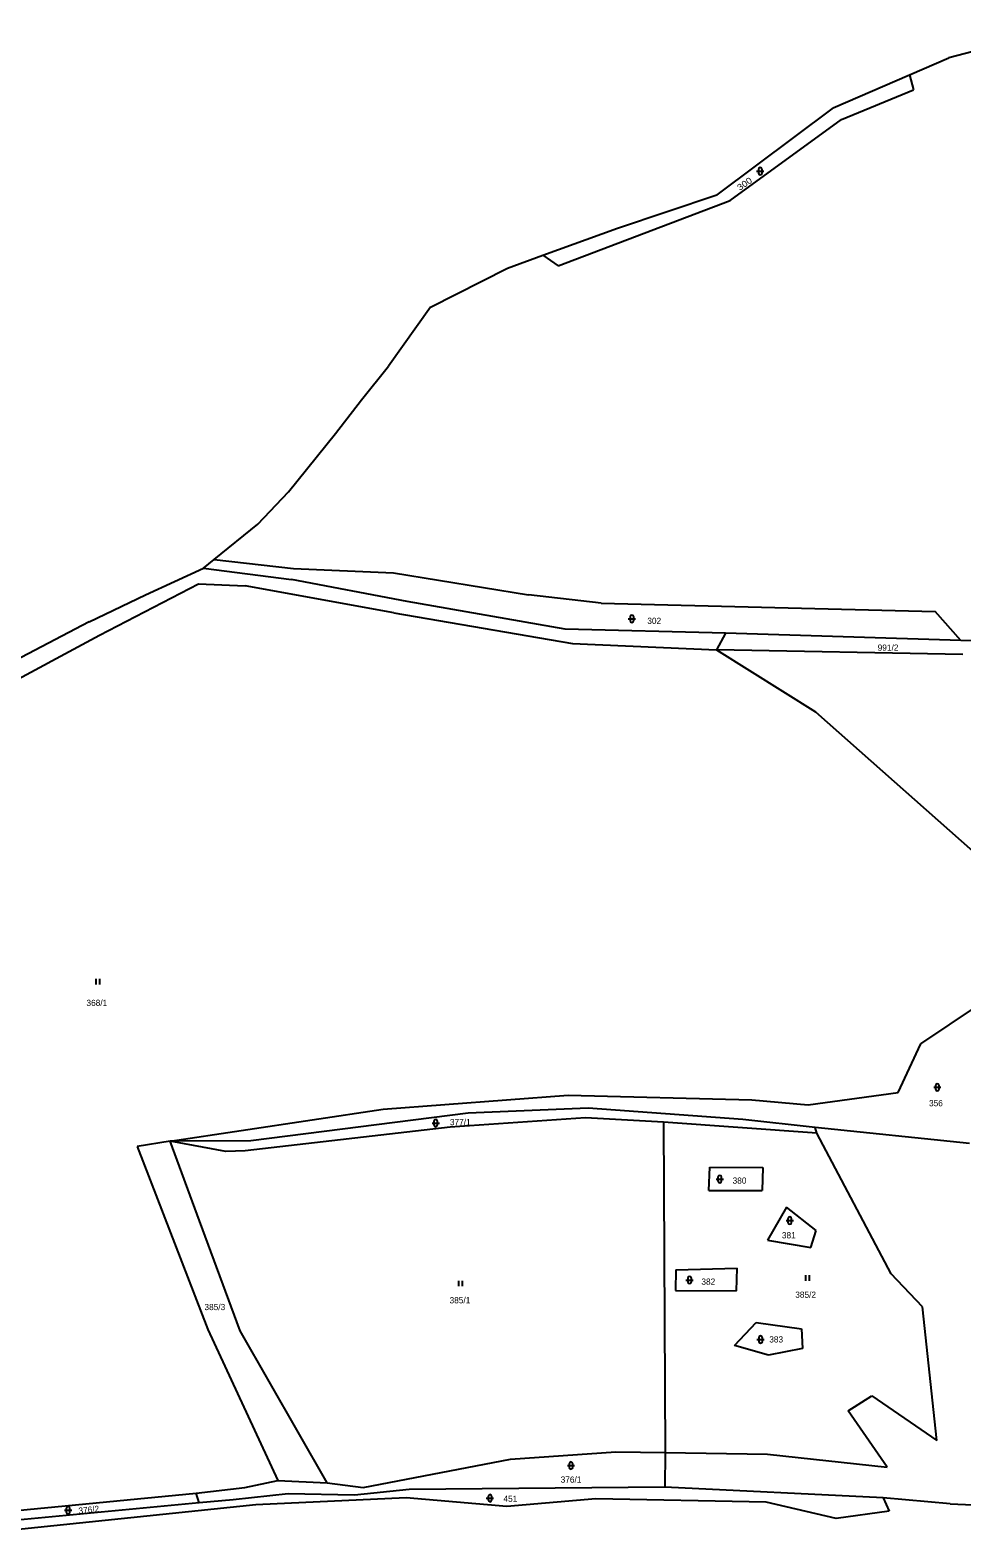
# Model space of a CAD drawing. Extents: x -754970 to -752637, y -970569 to -968179.
# Drawn here: x -754714.7 to -754459.1, y -968941.1 to -968527.7 of the extents above; entities that cross this region are included whole.
import ezdxf
from ezdxf.enums import TextEntityAlignment as Align

# ---------------------------------------------------------------- set-up
doc = ezdxf.new("R2010")
doc.units = 0
doc.header["$LTSCALE"] = 0.68
doc.layers.add('1', color=7, linetype='Continuous', lineweight=25)
doc.layers.add('3', color=7, linetype='Continuous', lineweight=25)
doc.layers.add('2', color=7, linetype='Continuous')

msp = doc.modelspace()

# ---------------------------------------------------------------- linework, layer by layer
at = {"layer": '1'}
for p, q in [((-754433.35, -968527.73), (-754462.74, -968535.32)), ((-754473.53, -968539.98), (-754462.74, -968535.32)), ((-754494.43, -968549), (-754473.53, -968539.98)), ((-754473.53, -968539.98), (-754472.43, -968544.13)), ((-754492.12, -968552.24), (-754472.43, -968544.13)), ((-754494.43, -968549), (-754526.37, -968572.84)), ((-754522.74, -968574.42), (-754492.12, -968552.24)), ((-754569.9, -968592.3), (-754522.74, -968574.42)), ((-754553.62, -968582), (-754526.37, -968572.84)), ((-754574.1, -968589.45), (-754553.62, -968582)), ((-754604.87, -968603.65), (-754583.78, -968592.98)), ((-754583.78, -968592.98), (-754574.1, -968589.45)), ((-754574.1, -968589.45), (-754569.9, -968592.3)), ((-754604.87, -968603.65), (-754616.39, -968619.89)), ((-754623.78, -968629.11), (-754616.39, -968619.89)), ((-754630.93, -968638.35), (-754623.78, -968629.11)), ((-754643.79, -968654.35), (-754630.93, -968638.35)), ((-754652.28, -968663.17), (-754643.79, -968654.35)), ((-754664.19, -968672.82), (-754652.28, -968663.17)), ((-754683.05, -968682.52), (-754667.13, -968675.2)), ((-754667.13, -968675.2), (-754664.19, -968672.82)), ((-754667.13, -968675.2), (-754643.04, -968678.37)), ((-754664.19, -968672.82), (-754642.5, -968675.3)), ((-754642.5, -968675.3), (-754615.07, -968676.54)), ((-754695.67, -968693.59), (-754668.51, -968679.52)), ((-754668.51, -968679.52), (-754655.68, -968680.06)), ((-754614.98, -968687.49), (-754655.68, -968680.06)), ((-754611.26, -968684.4), (-754643.04, -968678.37)), ((-754615.07, -968676.54), (-754578.01, -968682.54)), ((-754698.49, -968689.95), (-754683.05, -968682.52)), ((-754558.09, -968684.85), (-754578.01, -968682.54)), ((-754614.98, -968687.49), (-754565.96, -968695.92)), ((-754567.91, -968691.93), (-754611.26, -968684.4)), ((-754558.09, -968684.85), (-754466.45, -968687.14)), ((-754459.46, -968695.1), (-754466.45, -968687.14)), ((-754698.49, -968689.95), (-754722.7, -968702.69)), ((-754523.96, -968693.07), (-754567.91, -968691.93)), ((-754739.09, -968716.89), (-754695.67, -968693.59)), ((-754565.96, -968695.92), (-754526.43, -968697.59)), ((-754523.96, -968693.07), (-754526.43, -968697.59)), ((-754459.46, -968695.1), (-754523.96, -968693.07)), ((-754404.56, -968696.08), (-754459.46, -968695.1)), ((-754526.43, -968697.59), (-754499.27, -968714.58)), ((-754458.84, -968698.91), (-754526.43, -968697.59)), ((-754499.27, -968714.58), (-754450.52, -968757.76)), ((-754470.43, -968805.64), (-754454.59, -968795.02)), ((-754476.62, -968819.01), (-754470.43, -968805.64)), ((-754617.9, -968823.58), (-754567.13, -968819.69)), ((-754567.13, -968819.69), (-754516.79, -968821.03)), ((-754501.31, -968822.36), (-754476.62, -968819.01)), ((-754676.29, -968832.34), (-754617.9, -968823.58)), ((-754594.55, -968824.65), (-754654.17, -968832.26)), ((-754561.64, -968823.33), (-754594.55, -968824.65)), ((-754519.26, -968826.42), (-754561.64, -968823.33)), ((-754516.79, -968821.03), (-754501.31, -968822.36)), ((-754599.5, -968828.54), (-754655.68, -968835)), ((-754562.35, -968825.98), (-754599.5, -968828.54)), ((-754540.94, -968827.13), (-754562.35, -968825.98)), ((-754498.91, -968830.14), (-754540.94, -968827.13)), ((-754540.94, -968827.13), (-754540.53, -968917.68)), ((-754499.36, -968828.55), (-754519.26, -968826.42)), ((-754457.06, -968832.97), (-754499.36, -968828.55)), ((-754498.91, -968830.14), (-754499.36, -968828.55)), ((-754676.29, -968832.34), (-754685.32, -968833.76)), ((-754654.17, -968832.26), (-754676.29, -968832.34)), ((-754660.99, -968835.18), (-754676.29, -968832.34)), ((-754668.22, -968854.16), (-754676.29, -968832.34)), ((-754478.56, -968868.72), (-754498.91, -968830.14)), ((-754685.32, -968833.76), (-754665.99, -968883.99)), ((-754655.68, -968835), (-754660.99, -968835.18)), ((-754528.51, -968845.83), (-754528.27, -968839.45)), ((-754528.27, -968839.45), (-754513.72, -968839.56)), ((-754513.72, -968839.56), (-754513.95, -968845.88)), ((-754528.51, -968845.83), (-754513.95, -968845.88)), ((-754507.22, -968850.41), (-754512.5, -968859.46)), ((-754499.11, -968856.79), (-754507.22, -968850.41)), ((-754657.1, -968884.37), (-754668.22, -968854.16)), ((-754500.56, -968861.49), (-754499.11, -968856.79)), ((-754512.5, -968859.46), (-754500.56, -968861.49)), ((-754537.61, -968867.64), (-754537.73, -968873.32)), ((-754537.61, -968867.64), (-754520.74, -968867.17)), ((-754520.97, -968873.38), (-754520.74, -968867.17)), ((-754469.98, -968877.75), (-754478.56, -968868.72)), ((-754537.73, -968873.32), (-754520.97, -968873.38)), ((-754466.01, -968914.38), (-754469.98, -968877.75)), ((-754521.49, -968888.39), (-754515.57, -968882.07)), ((-754515.57, -968882.07), (-754503.1, -968883.75)), ((-754665.99, -968883.99), (-754646.77, -968925.35)), ((-754633.26, -968925.99), (-754657.1, -968884.37)), ((-754503.1, -968883.75), (-754502.87, -968889.2)), ((-754512.15, -968891), (-754521.49, -968888.39)), ((-754502.87, -968889.2), (-754512.15, -968891)), ((-754490.29, -968906.28), (-754483.82, -968902.2)), ((-754483.82, -968902.2), (-754466.01, -968914.38)), ((-754479.67, -968921.7), (-754490.29, -968906.28)), ((-754623.34, -968927.26), (-754582.96, -968919.52)), ((-754582.96, -968919.52), (-754554.04, -968917.55)), ((-754554.04, -968917.55), (-754540.53, -968917.68)), ((-754540.53, -968917.68), (-754540.6, -968927.18)), ((-754540.53, -968917.68), (-754512.46, -968918.11)), ((-754512.46, -968918.11), (-754479.67, -968921.7)), ((-754669.15, -968928.87), (-754655.78, -968927.32)), ((-754655.78, -968927.32), (-754646.77, -968925.35)), ((-754646.77, -968925.35), (-754633.26, -968925.99)), ((-754633.26, -968925.99), (-754623.34, -968927.26)), ((-754610.73, -968927.88), (-754625.73, -968929.36)), ((-754540.6, -968927.18), (-754610.73, -968927.88)), ((-754480.7, -968930.14), (-754540.6, -968927.18)), ((-754742.36, -968935.85), (-754669.15, -968928.87)), ((-754668.37, -968931.48), (-754741.45, -968938.5)), ((-754652.76, -968932.04), (-754739.66, -968941.09)), ((-754668.37, -968931.48), (-754669.15, -968928.87)), ((-754659.01, -968930.63), (-754668.37, -968931.48)), ((-754643.88, -968929.01), (-754659.01, -968930.63)), ((-754611.53, -968930.15), (-754652.76, -968932.04)), ((-754625.73, -968929.36), (-754643.88, -968929.01)), ((-754583.94, -968932.46), (-754611.53, -968930.15)), ((-754559.52, -968930.35), (-754583.94, -968932.46)), ((-754512.79, -968931.33), (-754559.52, -968930.35)), ((-754493.58, -968935.77), (-754512.79, -968931.33)), ((-754480.7, -968930.14), (-754479.08, -968933.73)), ((-754462.39, -968931.72), (-754480.7, -968930.14)), ((-754462.39, -968931.72), (-754430.03, -968933.19)), ((-754479.08, -968933.73), (-754493.58, -968935.77))]:
    msp.add_line(p, q, dxfattribs=at)
at = {"layer": '3'}
for p, q in [((-754515.441, -968566.401), (-754513.439, -968566.401)), ((-754514.941, -968565.901), (-754514.941, -968566.902)), ((-754513.939, -968566.902), (-754513.939, -968565.901)), ((-754550.641, -968689.101), (-754548.639, -968689.101)), ((-754550.141, -968688.601), (-754550.141, -968689.602)), ((-754549.139, -968689.602), (-754549.139, -968688.601)), ((-754696.621, -968789.36), (-754696.621, -968787.86)), ((-754695.62, -968789.36), (-754695.62, -968787.86)), ((-754466.881, -968817.571), (-754464.879, -968817.571)), ((-754466.381, -968817.071), (-754466.381, -968818.072)), ((-754465.379, -968818.072), (-754465.379, -968817.071)), ((-754604.461, -968827.361), (-754602.459, -968827.361)), ((-754603.961, -968826.861), (-754603.961, -968827.862)), ((-754602.959, -968827.862), (-754602.959, -968826.861)), ((-754526.541, -968842.721), (-754524.539, -968842.721)), ((-754526.041, -968842.221), (-754526.041, -968843.222)), ((-754525.039, -968843.222), (-754525.039, -968842.221)), ((-754506.851, -968853.601), (-754506.851, -968854.602)), ((-754505.849, -968854.602), (-754505.849, -968853.601)), ((-754507.351, -968854.101), (-754505.349, -968854.101)), ((-754534.321, -968869.901), (-754534.321, -968870.902)), ((-754533.319, -968870.902), (-754533.319, -968869.901)), ((-754501.911, -968870.61), (-754501.911, -968869.11)), ((-754500.91, -968870.61), (-754500.91, -968869.11)), ((-754597.121, -968872.1), (-754597.121, -968870.6)), ((-754596.12, -968872.1), (-754596.12, -968870.6)), ((-754534.821, -968870.401), (-754532.819, -968870.401)), ((-754515.351, -968886.721), (-754513.349, -968886.721)), ((-754514.851, -968886.221), (-754514.851, -968887.222)), ((-754513.849, -968887.222), (-754513.849, -968886.221)), ((-754567.351, -968921.261), (-754565.349, -968921.261)), ((-754566.851, -968920.761), (-754566.851, -968921.762)), ((-754565.849, -968921.762), (-754565.849, -968920.761)), ((-754589.581, -968930.211), (-754587.579, -968930.211)), ((-754589.081, -968929.711), (-754589.081, -968930.712)), ((-754588.079, -968930.712), (-754588.079, -968929.711)), ((-754705.291, -968933.531), (-754703.289, -968933.531)), ((-754704.791, -968933.031), (-754704.791, -968934.032)), ((-754703.789, -968934.032), (-754703.789, -968933.031))]:
    msp.add_line(p, q, dxfattribs=at)
for centre, start, end in [((-754514.44, -968565.9009), 0, 180), ((-754514.44, -968566.9009), 180, 359.98789), ((-754549.64, -968688.6009), 0, 180), ((-754549.64, -968689.6009), 180, 359.98789), ((-754465.88, -968817.0709), 0, 180), ((-754465.88, -968818.0709), 180, 359.98789), ((-754603.46, -968826.8609), 0, 180), ((-754603.46, -968827.8609), 180, 359.98789), ((-754525.54, -968842.2209), 0, 180), ((-754525.54, -968843.2209), 180, 359.98789), ((-754506.35, -968853.6009), 0, 180), ((-754506.35, -968854.6009), 180, 359.98789), ((-754533.82, -968869.9009), 0, 180), ((-754533.82, -968870.9009), 180, 359.98789), ((-754514.35, -968886.2209), 0, 180), ((-754514.35, -968887.2209), 180, 359.98789), ((-754566.35, -968920.7609), 0, 180), ((-754566.35, -968921.7609), 180, 359.98789), ((-754588.58, -968929.7109), 0, 180), ((-754588.58, -968930.7109), 180, 359.98789), ((-754704.29, -968933.0309), 0, 180), ((-754704.29, -968934.0309), 180, 359.98789)]:
    msp.add_arc(centre, 0.5, start, end, dxfattribs=at)

# ---------------------------------------------------------------- texts
at = {"layer": '2', "width": 1.15}
msp.add_text('300', height=1.7, rotation=35, dxfattribs=at).set_placement((-754518.2575, -968570.5634), align=Align.CENTER)
at = {"layer": '2'}
for s, p in [('302', (-754543.519, -968690.525)), ('991/2', (-754479.39, -968697.875)), ('368/1', (-754696.4, -968795.265)), ('356', (-754466.259, -968822.765)), ('377/1', (-754596.72, -968827.955)), ('380', (-754520.129, -968843.995)), ('381', (-754506.609, -968858.975)), ('382', (-754528.689, -968871.695)), ('385/2', (-754502, -968875.275)), ('385/3', (-754664.04, -968878.655)), ('385/1', (-754596.81, -968876.795)), ('383', (-754510.079, -968887.525)), ('376/1', (-754566.34, -968925.965)), ('451', (-754582.979, -968931.205))]:
    msp.add_text(s, height=1.7, dxfattribs=at).set_placement(p, align=Align.CENTER)
msp.add_text('376/2', height=1.7, rotation=6, dxfattribs=at).set_placement((-754698.5103, -968934.2278), align=Align.CENTER)

doc.saveas('drawing.dxf')
